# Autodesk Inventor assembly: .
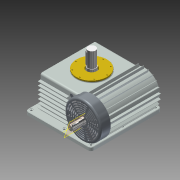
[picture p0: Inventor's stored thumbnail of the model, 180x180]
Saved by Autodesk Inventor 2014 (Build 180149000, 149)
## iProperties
Created: 2002-08
Part Number: .
Description: WormGear.iam.
Document SubType Name: Assembly
Mass: 41449.1 g
Surface Area: 29030.7 cm^2
Volume: 14351.8 cm^3
Density: 2.88808 g/cm^3
Shininess: 64.0
Length Units: 11269
Angle Units: 11279
Time Units: 11290
Mass Units: 11283
Length Display Precision: 3
Angle Display Precision: 2
ProtocolID: P00020808151709057
Protocol: P00020808151709057<@PID>[Version]<@EL>Version=2.2<@EL>[BaseView]<@EL>H2=582<@EL>W2=350<@EL>Top=93<@EL>Left=550<@EL>OnTop=0<@EL>InOpt=0<@EL>UpdateAll=0<@EL>Enabl
Density: 0.0
Volumn: 0.0
Area: 0.0
PropertySet Name: Model Information
Control State: 0
Master: False
Checked Out: False
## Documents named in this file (24)
- C:\Users\iTools\Desktop\tutorial files\Worm Gear\WormGear.iam
- C:\Users\iTools\Desktop\tutorial files\Worm Gear\gear-box.ipt
- C:\Users\iTools\Desktop\tutorial files\Worm Gear\worm.ipt
- C:\Users\iTools\Desktop\tutorial files\Worm Gear\b_holder.ipt
- C:\Users\iTools\Desktop\tutorial files\Worm Gear\holder_1.ipt
- C:\Users\iTools\Desktop\tutorial files\Worm Gear\Shaft_out.ipt
- C:\Users\iTools\Desktop\tutorial files\Worm Gear\cover.ipt
- C:\Users\iTools\Desktop\tutorial files\Worm Gear\fan.ipt
- C:\Users\iTools\Desktop\tutorial files\Worm Gear\LockWasher.ipt
- C:\Users\iTools\Desktop\tutorial files\Worm Gear\LockNut.ipt
- C:\Users\iTools\Desktop\tutorial files\Worm Gear\Sealing.ipt
- C:\Users\iTools\Desktop\tutorial files\Worm Gear\bonnet.ipt
- C:\Users\iTools\Desktop\tutorial files\Worm Gear\holder_2.ipt
- C:\Users\iTools\Desktop\tutorial files\Worm Gear\WormGear.ipt
- C:\Users\iTools\Desktop\tutorial files\Worm Gear\Bearing_in1.ipt
- C:\Users\iTools\Desktop\tutorial files\Worm Gear\tap_bearing_1.ipt
- C:\Users\iTools\Desktop\tutorial files\Worm Gear\holder_out.ipt
- C:\Users\iTools\Desktop\tutorial files\Worm Gear\top_cover.ipt
- C:\Users\iTools\Desktop\tutorial files\Worm Gear\tap_bearing_2.ipt
- C:\Users\iTools\Desktop\tutorial files\Worm Gear\sealing_out.ipt
- C:\Users\iTools\Desktop\tutorial files\Worm Gear\input_key.ipt
- C:\Users\iTools\Desktop\tutorial files\Worm Gear\output_key.ipt
- C:\Users\iTools\Desktop\tutorial files\Worm Gear\Bearing_in2.ipt
- C:\Users\iTools\Desktop\tutorial files\Worm Gear\side_cover.ipt
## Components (24 placed, 23 different names)
1. gear-box.ipt:1 — Mate:1, Mate:2, Mate:6, Mate:7, Mate:9, Mate:10, Mate:11, Flush:1, Flush:2, Flush:3, Flush:5, Flush:6, Mate:30, Flush:7, Mate:31, Insert:3, Flush:9
2. Worm gearing 1/25, 165:1 — Mate:1, Mate:3, Mate:4, Rotation:1, Mate:5, Mate:8, Mate:24, Mate:25, Mate:26
3. Worm gearing 1/25, 165_2:1 — Mate:2, Mate:3, Mate:4, Rotation:1, Flush:4, Mate:12, Mate:13, Mate:22, Mate:23
4. Bearing SKF 3309:1 — Mate:5, Mate:6
5. Bearing SKF 6009:1 — Mate:7, Mate:8
6. cover:1 — Mate:9, Mate:10, Flush:1
7. fan:1 — Mate:11, Mate:35
8. Lockwasher DIN 5406 MB9:1
9. Locknut KM  9 DIN 981:1
10. top_cover.ipt:1 — Flush:5, Mate:14, Mate:17, Mate:20
11. Sealing A 40x52x7 DIN 3760-NB:1 — Mate:30, Flush:7, Mate:31, Flush:8, Mate:34
12. bonnet:1 — Flush:8, Mate:34, Mate:35
13. holder_1:1 — Flush:2
14. holder_2:1 — Flush:3
15. holder_out.ipt:1 — Flush:4, Mate:21, Mate:22, Mate:33
16. holder_out.ipt:2 — Mate:12, Mate:13, Mate:21
17. b_holder.ipt:1 — Flush:6, Mate:15, Mate:16
18. Bearing SKF 30302_2:1 — Mate:15, Mate:16, Mate:32
19. Bearing SKF 30302:1 — Mate:14, Mate:17, Mate:18, Mate:19
20. Output Shaft:1 — Mate:18, Mate:19, Mate:23, Mate:27, Mate:28, Mate:29, Mate:32, Mate:33
21. Sealing IS0 6194/1 55x72x8 Type 5:1 — Mate:20, Insert:3
22. Key 10h9x8h11x22 ISO R773-A:1 — Mate:24, Mate:25, Mate:26
23. Key 14h9x9h11x80 ISO R773-A:1 — Mate:27, Mate:28, Mate:29
24. side_cover:1 — Flush:9
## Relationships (46: Mate 35, Flush 9, RelateRotation 1, Insert 1)
- Mate:1: gear-box.ipt:1 ↔ Worm gearing 1/25, 165:1
- Mate:2: gear-box.ipt:1 ↔ Worm gearing 1/25, 165_2:1
- Mate:3: Worm gearing 1/25, 165:1 ↔ Worm gearing 1/25, 165_2:1
- Mate:4: Worm gearing 1/25, 165:1 ↔ Worm gearing 1/25, 165_2:1
- Rotation:1 [RelateRotation]: Worm gearing 1/25, 165:1 ↔ Worm gearing 1/25, 165_2:1
- Mate:5: Worm gearing 1/25, 165:1 ↔ Bearing SKF 3309:1
- Mate:6: gear-box.ipt:1 ↔ Bearing SKF 3309:1
- Mate:7: gear-box.ipt:1 ↔ Bearing SKF 6009:1
- Mate:8: Worm gearing 1/25, 165:1 ↔ Bearing SKF 6009:1
- Mate:9: gear-box.ipt:1 ↔ cover:1
- Mate:10: gear-box.ipt:1 ↔ cover:1
- Mate:11: gear-box.ipt:1 ↔ fan:1
- Flush:1: gear-box.ipt:1 ↔ cover:1
- Flush:2: gear-box.ipt:1 ↔ holder_1:1
- Flush:3: gear-box.ipt:1 ↔ holder_2:1
- Flush:4: Worm gearing 1/25, 165_2:1 ↔ holder_out.ipt:1
- Mate:12: Worm gearing 1/25, 165_2:1 ↔ holder_out.ipt:2
- Mate:13: Worm gearing 1/25, 165_2:1 ↔ holder_out.ipt:2
- Flush:5: gear-box.ipt:1 ↔ top_cover.ipt:1
- Mate:14: top_cover.ipt:1 ↔ Bearing SKF 30302:1
- Flush:6: gear-box.ipt:1 ↔ b_holder.ipt:1
- Mate:15: b_holder.ipt:1 ↔ Bearing SKF 30302_2:1
- Mate:16: b_holder.ipt:1 ↔ Bearing SKF 30302_2:1
- Mate:17: top_cover.ipt:1 ↔ Bearing SKF 30302:1
- Mate:18: Bearing SKF 30302:1 ↔ Output Shaft:1
- Mate:19: Bearing SKF 30302:1 ↔ Output Shaft:1
- Mate:20: top_cover.ipt:1 ↔ Sealing IS0 6194/1 55x72x8 Type 5:1
- Mate:21: holder_out.ipt:1 ↔ holder_out.ipt:2
- Mate:22: Worm gearing 1/25, 165_2:1 ↔ holder_out.ipt:1
- Mate:23: Worm gearing 1/25, 165_2:1 ↔ Output Shaft:1
- Mate:24: Worm gearing 1/25, 165:1 ↔ Key 10h9x8h11x22 ISO R773-A:1
- Mate:25: Worm gearing 1/25, 165:1 ↔ Key 10h9x8h11x22 ISO R773-A:1
- Mate:26: Worm gearing 1/25, 165:1 ↔ Key 10h9x8h11x22 ISO R773-A:1
- Mate:27: Output Shaft:1 ↔ Key 14h9x9h11x80 ISO R773-A:1
- Mate:28: Output Shaft:1 ↔ Key 14h9x9h11x80 ISO R773-A:1
- Mate:29: Output Shaft:1 ↔ Key 14h9x9h11x80 ISO R773-A:1
- Mate:30: gear-box.ipt:1 ↔ Sealing A 40x52x7 DIN 3760-NB:1
- Flush:7: gear-box.ipt:1 ↔ Sealing A 40x52x7 DIN 3760-NB:1
- Mate:31: gear-box.ipt:1 ↔ Sealing A 40x52x7 DIN 3760-NB:1
- Mate:32: Bearing SKF 30302_2:1 ↔ Output Shaft:1
- Insert:3: gear-box.ipt:1 ↔ Sealing IS0 6194/1 55x72x8 Type 5:1
- Mate:33: holder_out.ipt:1 ↔ Output Shaft:1
- Flush:8: Sealing A 40x52x7 DIN 3760-NB:1 ↔ bonnet:1
- Mate:34: Sealing A 40x52x7 DIN 3760-NB:1 ↔ bonnet:1
- Mate:35: fan:1 ↔ bonnet:1
- Flush:9: gear-box.ipt:1 ↔ side_cover:1
